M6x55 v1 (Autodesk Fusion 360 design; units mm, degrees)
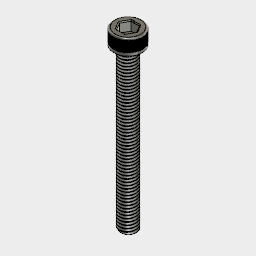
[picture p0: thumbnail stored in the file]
sketch "スケッチ1"
  circle C1 centre (0, 0) radius 3
  circle C2 centre (0, 0) radius 5
  dimension "d1" diameter C1 = 6
  dimension "d2" diameter C2 = 10
extrude "押し出し1" new body sketch "スケッチ1" blind 5.8
sketch "スケッチ2" plane through (0, 0, 5.8) normal (0, 0, 1) x axis (-1, 0, 0)
  line L1 (-1.4722, -2.55) -> (-2.9445, 0)
  line L2 (1.4722, -2.55) -> (-1.4722, -2.55)
  line L3 (2.9445, 0) -> (1.4722, -2.55)
  line L4 (1.4722, 2.55) -> (2.9445, 0)
  line L5 (-1.4722, 2.55) -> (1.4722, 2.55)
  line L6 (-2.9445, 0) -> (-1.4722, 2.55)
  circle C1 centre (0, 0) radius 5
  dimension "d5" distance L2 L5 = 5.1
work_plane "作業平面" sketch "スケッチ2" AlongDistance -0.75
extrude "押し出し2" cut sketch "スケッチ2" profile of L1 L2 L3 L4 L5 L6 against normal blind 3.3
chamfer "面取り" distance 0.3
sketch "スケッチ3" plane through (0, 0, 5.05) normal (0, 0, 1) x axis (1, 0, 0)
  line L1 (-0.05, 4.9497) -> (-0.05, 4.9997)
  line L2 (0.05, 4.9497) -> (-0.05, 4.9497)
  line L3 (0.05, 4.9997) -> (0.05, 4.9497)
  circle C1 centre (0, 0) radius 5
  point P4 (-0.05, 4.9497)
  point P5 (0.05, 4.9497)
  point P3 (-0.05, 4.9997)
  point P6 (0.05, 4.9997)
  dimension "d18" distance P4 P5 = 0.1
  dimension "d19" distance P3 P4 = 0.05
  dimension "d20" distance P5 P6 = 0.05 (= "d19")
extrude "押し出し3" cut sketch "スケッチ3" against normal blind 3.6
work_axis "作業軸"
circular_pattern "C パターン" countU 100 TotalAngle 360
fillet "フィレット1" radius 0.6
extrude "押し出し4" add sketch "スケッチ1" profile of C1 blind -55
thread "ねじ"
fillet "フィレット2" sketch "スケッチ3" radius 0.5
